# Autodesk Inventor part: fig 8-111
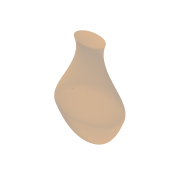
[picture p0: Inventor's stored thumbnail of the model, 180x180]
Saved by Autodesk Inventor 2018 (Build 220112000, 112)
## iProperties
Created: 2004-05
Part Number: fig 8-111
Document SubType Name: Modeling
Designer: CADCIM Technologies
Manufacturer: Standard
Standards Organization: Custom
Density: 1 g/cm^3
Material: Generic
Appearance: Default
Author: CADCIM Technologies
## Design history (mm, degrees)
sketch "Sketch4"
  geometry: 1 further point; 1 other entity
  constraints: 2 other
workplane "Work Plane2"
sketch "Sketch5"
  geometry: 1 further point; 1 other entity
  constraints: 2 other
feature "LoftSrf1" sketch "Sketch5" dims "d4" = 20, "d5" = 110 deg, "d6" = 40, "d7" = 70 deg
patch "Boundary Patch2" dims "d10" = 0, "d11" = 0
patch "Boundary Patch3" dims "d13" = 0, "d14" = 0
body "Srf1"
body "Srf3"
body "Srf4"
other parameters: "d3" = 33.5
